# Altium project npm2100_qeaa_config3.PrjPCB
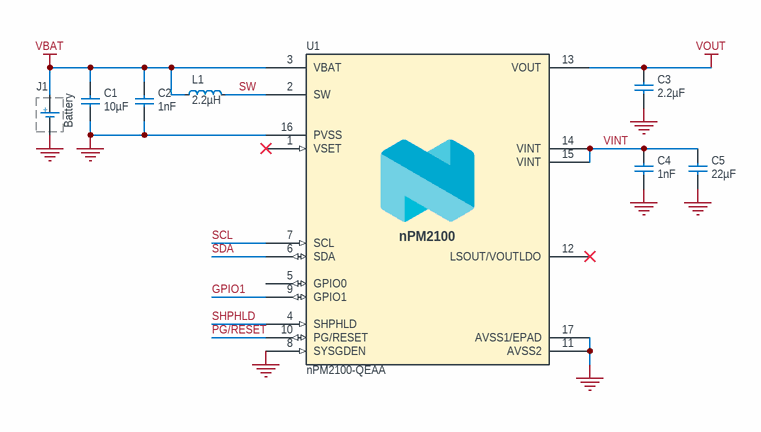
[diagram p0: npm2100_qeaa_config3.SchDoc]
1 sheet, 8 parts. Net scope: global (net labels, ports and power ports of the same name join across sheets).
Board file: npm2100_qeaa_config3.PcbDoc

## Sheet npm2100_qeaa_config3.SchDoc: nPM2100-QxAA Ref. Layout Config. 1
size A4; Revision: 0.2; SheetNumber: 1; SheetTotal: 1; DrawnBy: DABA; DocumentSize: A4; BoardTitle: nPM2100-QxAA Ref. Layout Config. 1; PCAName: nPM2100-QEAA; RefLayoutTitle: Reference Layout Config. 3: Minimum Size; Device: nPM2100-QEAA; Classification: Public

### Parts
C1  10µF  [CAPC1005X04L_C2]
C2  1nF  [CAPC0603X03L_C]
C3  2.2µF  [CAPC0603X03L_C]
C4  1nF  [CAPC0603X03L_C]
C5  22µF  [CAPC1005X04L_C2]
J1  Battery  [TP_2x1mm_TH]  (graphical)
L1  2.2µH  [INDC1005X04L]
U1  nPM2100-QEAA  [QFN65P400X400X65_HS-17N]

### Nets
GND: C1.1 C2.1 C3.1 C4.1 C5.1 J1.1(GND) U1.8(SYSGDEN) U1.11(AVSS2) U1.16(PVSS) U1.17(AVSS1/EPAD)
VBAT: C1.2 C2.2 J1.2(V+) L1.1 U1.3(VBAT)
VOUT: C3.2 U1.13(VOUT)
GPIO1: U1.9(GPIO1)
PG/RESET: U1.10(PG/RESET)
SCL: U1.7(SCL)
SDA: U1.6(SDA)
SHPHLD: U1.4(SHPHLD)
SW: L1.2 U1.2(SW)
VINT: C4.2 C5.2 U1.14(VINT) U1.15(VINT)

Not connected (* = marked no-connect by the designer): U1 1(VSET)* 5(GPIO0) 12(LSOUT/VOUTLDO)*

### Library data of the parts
C1 = C0402-10µ-6.3V-X5R-GRM155R60J106ME05D: Capacitor, X5R, ±20%, 6.3V; Manufacturer: Murata; Part number NEMS: 100200554; Component Status: Active; Pad Count: 2; Artikkelnr Noca: N.A.
C2 C4 = C0201-1n0-50V-X7R: Capacitor, X7R, ±10pF, 50V; Manufacturer: Murata; Manufacturer Part Number: GRM033R71H102KA12D; Part number NEMS: 100200404; Component Status: Active; Pad Count: 2; Artikkelnr Noca: N.A.
C3 = C0201-2.2µ-6V3-X5R-GRM033R60J225ME01: Capacitor, Ceramic, X5R, ±20%, 6.3V; Manufacturer: Murata; Part number NEMS: 100200660; Component Status: Active; Pad Count: 2; Note: -55°C ~ 125°C; Artikkelnr Noca: N.A.
C5 = C0402-22µ-6.3V-X5R-GRM158R60J226ME01D: Capacitor, X5R, ±20%, 6.3V; Manufacturer: Murata; Part number NEMS: 100200555; Component Status: Active; Pad Count: 2; Artikkelnr Noca: N.A.
J1 = Battery_TP: Manufacturer: N.A.; Part number NEMS: 101800006; Component Status: Active; Pad Count: 3
L1 = L0402-2µ2-PLEA67BBA2R2M-1PT00: Inductor, 500mA, ±20%, 620 mOhms; Manufacturer: TDK Corporation; Part number NEMS: 100300496; Component Status: Active; Pad Count: 2; Note: Power Inductor ±20%; Artikkelnr Noca: N.A.
U1 = nPM2100-QEAA: Boost converter companion PMIC for maximum energy extraction of primary (no-rechargeable) batteries; Manufacturer: Nordic Semiconductor; Part number NEMS: 102000298; Component Status: Active; Pad Count: 17; Note: N.A.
